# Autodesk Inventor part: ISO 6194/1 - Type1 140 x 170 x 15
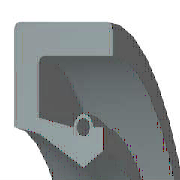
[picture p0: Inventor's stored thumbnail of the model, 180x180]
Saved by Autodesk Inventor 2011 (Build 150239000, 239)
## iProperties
IsCustomPart: 0
Created: 2010-02
Part Number: ISO 6194/1 - Type1 140 x 170 x 15
Material: Rubber
Description: Rotary shaft lip type seals
Document SubType Name: Modeling
Standard: ISO 6194/1
Designer: 129877
Standard Revision: First edition 1982-10-01
Standards Organization: ISO
Language: en-US
Size Designation: Type1 140 x 170 x 15
Categories: <MemberInstance><Categories><Category DisplayName="Shaft Parts" InternalName="7f7aeb1f-a693-4053-b835-cee3144e0d98" Mnemonic="SHFT"><Category DisplayName="Seali
Density: 0.93 g/cm^3
Mass: 51.5123 g
Surface Area: 366.495 cm^2
Volume: 55.3895 cm^3
Author: 129877
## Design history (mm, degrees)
revolve "Body" stored, may be unused: angle "d17" = 90 deg
revolve "Spring1" stored, may be unused: angle "d18" = 90 deg
body "Solid1"
sketch "Sketch1"
  geometry: L1 (0, 85)-(15, 85); L2 (15, 85)-(15, 81.75); L3 (15, 81.75)-(3.75, 81.75); L4 (0, 85)-(0, 74.5); L5 (0, 74.5)-(3.75, 73.75); L6 (3.75, 73.75)-(10.5, 70); L7 (10.5, 70)-(0, 70); L8 (13.5, 71.875)-(13.5, 74.5); L9 (0, 0)-(9.586, 0) reference; L10 (10.5, 70)-(13.5, 71.875); L11 (0, 18)-(0, -3) reference; L12 (-1.917, 0)-(11.503, 0) reference; L13 (9, 74.5)-(3.75, 75.55); L14 (3.75, 75.55)-(3.75, 81.75); L15 (13.5, 74.5)-(12, 74.5); C1 r 0.975 at (10.5, 74.5); A1 r 1.5 centre (10.5, 74.5) between (12, 74.5) and (9, 74.5)
  constraints: 26 end point, 5 horizontal alignment, 4 perpendicular, 2 centre point, 2 collinear, 2 horizontal, 2 parallel, 2 point on circle, 2 point on line, 2 vertical alignment, 1 coincident
  dimensions: "d0" = 170 diameter of L1 L9 (= SD2); "d1" = 143.75 diameter of L8.start L9 (= ABDM); "d2" = 3.25 distance of L1.end L2.end (computed from SD); "d3" = 1.95 diameter of C1 (= SPDI); "d4" = 3 diameter of A1 (= SPDA); "d5" = 140 diameter of L6.end L9 (= NND); "d6" = 147.5 diameter of L5.end L9 (= TKDM); "d7" = 149 diameter of L4.end L9 (= HLDM); "d8" = 10.5 distance from line of C1.centre L4 (= SPDST); "d9" = 13.5 distance between parallel lines of L8 L4 (= SDI); "d10" = 15 distance between parallel lines of L2 L4 (= SWDT); "d12" = 3.75 distance between parallel lines of L14 L4 (= SD)
fillet "Fillet1" dims "d11" = 1 (= RR)
other parameters: "SD2" = 170 [user parameter; used in 1 equation term], "SWDT" = 15 [user parameter; used in 1 equation term], "RR" = 1 [user parameter; used in 1 equation term], "SD" = 3.75 [user parameter; used in 2 equation terms], "NND" = 140 [user parameter; used in 1 equation term], "SPDA" = 3 [user parameter; used in 1 equation term], "SPDI" = 1.95 [user parameter; used in 1 equation term], "TKDM" = 147.5 [user parameter; used in 1 equation term], "HLDM" = 149 [user parameter; used in 1 equation term], "ABDM" = 143.75 [user parameter; used in 1 equation term], "SDI" = 13.5 [user parameter; used in 1 equation term], "SPDST" = 10.5 [user parameter; used in 1 equation term], "d13" = 0, "d14" = 0, "d15" = 0, "LAB" = 0.75 [user parameter]
